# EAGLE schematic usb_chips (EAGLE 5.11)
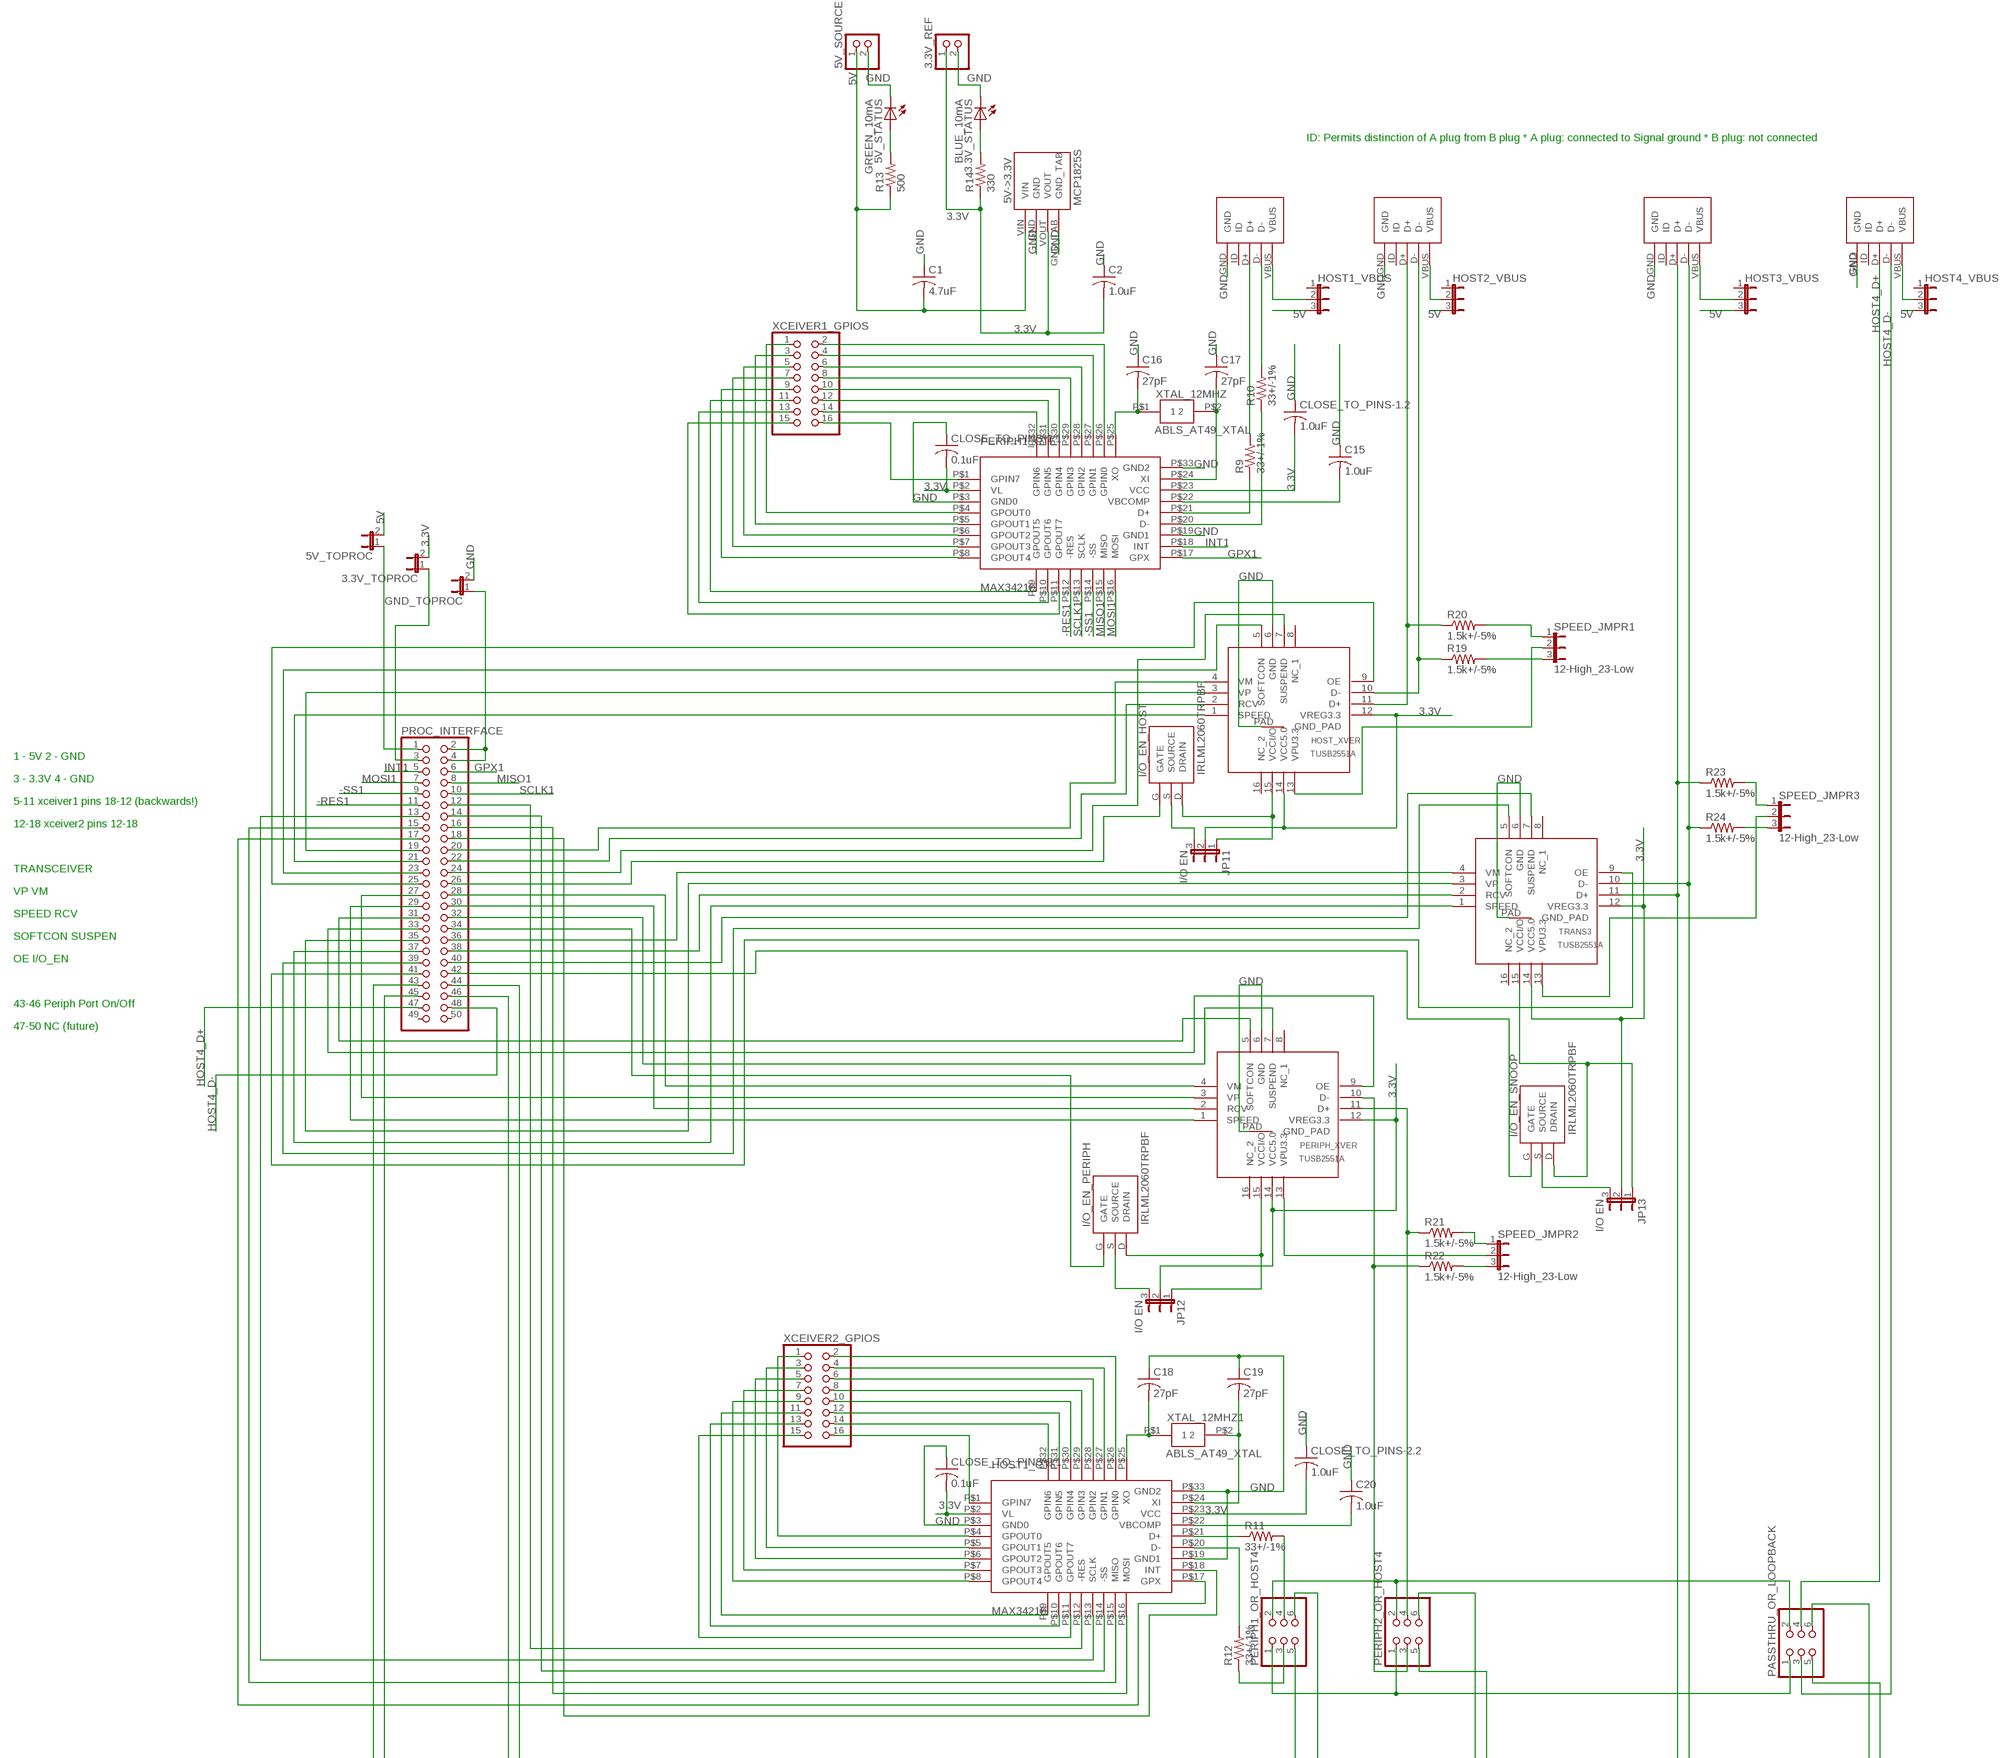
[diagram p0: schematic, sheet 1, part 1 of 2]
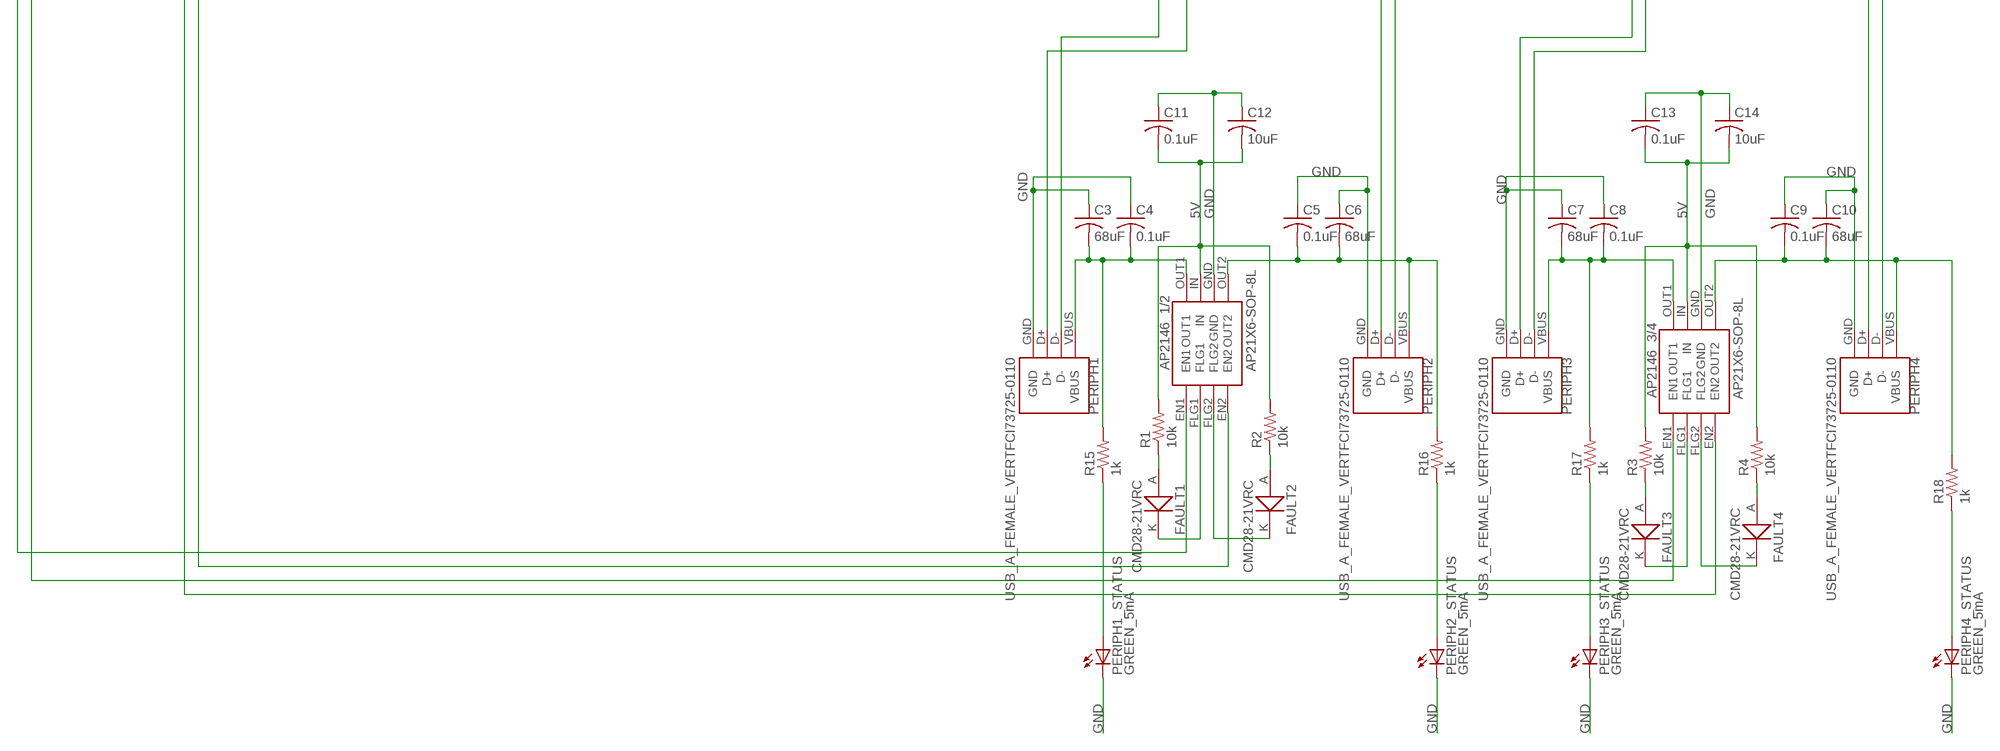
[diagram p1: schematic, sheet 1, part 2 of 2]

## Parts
3.3V_REF  PINHD-1X2  [1X02]
3.3V_STATUS  BLUE_10mA  LEDCHIP-LED0805  [CHIP-LED0805]
3.3V_TOPROC  JP1E  [JP1]
5V->3.3V  MCP1825S  [MCP1825S]
5V_SOURCE  PINHD-1X2  [1X02]
5V_STATUS  GREEN_10mA  LEDCHIP-LED0805  [CHIP-LED0805]
5V_TOPROC  JP1E  [JP1]
AP2146_1/2  AP21X6-SOP-8L  [AP21X6]
AP2146_3/4  AP21X6-SOP-8L  [AP21X6]
C1  4.7uF  C-USC0805  [C0805]
C2  1.0uF  C-USC0805  [C0805]
C3  68uF  C-USC0805  [C0805]
C4  0.1uF  C-USC0805  [C0805]
C5  0.1uF  C-USC0805  [C0805]
C6  68uF  C-USC0805  [C0805]
C7  68uF  C-USC0805  [C0805]
C8  0.1uF  C-USC0805  [C0805]
C9  0.1uF  C-USC0805  [C0805]
C10  68uF  C-USC0805  [C0805]
C11  0.1uF  C-USC0805  [C0805]
C12  10uF  C-USC0805  [C0805]
C13  0.1uF  C-USC0805  [C0805]
C14  10uF  C-USC0805  [C0805]
C15  1.0uF  C-USC0805  [C0805]
C16  27pF  C-USC0805  [C0805]
C17  27pF  C-USC0805  [C0805]
C18  27pF  C-USC0805  [C0805]
C19  27pF  C-USC0805  [C0805]
C20  1.0uF  C-USC0805  [C0805]
CLOSE_TO_PINS-1.1  0.1uF  C-USC0805  [C0805]
CLOSE_TO_PINS-1.2  1.0uF  C-USC0805  [C0805]
CLOSE_TO_PINS-2.1  0.1uF  C-USC0805  [C0805]
CLOSE_TO_PINS-2.2  1.0uF  C-USC0805  [C0805]
FAULT1  CMD28-21VRC  [CMD28-21VRC]
FAULT2  CMD28-21VRC  [CMD28-21VRC]
FAULT3  CMD28-21VRC  [CMD28-21VRC]
FAULT4  CMD28-21VRC  [CMD28-21VRC]
GND_TOPROC  JP1E  [JP1]
HOST1  USB_MICRO_B_FEMALE  [USB_MICRO_B_FEMALE]
HOST1_CTL  MAX3421E  [MAX3421]
HOST1_VBUS  JP2E  [JP2]
HOST2  USB_MICRO_B_FEMALE  [USB_MICRO_B_FEMALE]
HOST2_VBUS  JP2E  [JP2]
HOST3  USB_MICRO_B_FEMALE  [USB_MICRO_B_FEMALE]
HOST3_VBUS  JP2E  [JP2]
HOST4  USB_MICRO_B_FEMALE  [USB_MICRO_B_FEMALE]
HOST4_VBUS  JP2E  [JP2]
HOST_XVER  TUSB2551A  [S-PVQFN-N16]
I/O_EN_HOST  IRLML2060TRPBF  [SOT-23_IRLML2060TRPBF]
I/O_EN_PERIPH  IRLML2060TRPBF  [SOT-23_IRLML2060TRPBF]
I/O_EN_SNOOP  IRLML2060TRPBF  [SOT-23_IRLML2060TRPBF]
JP11  I/O EN  JP2E  [JP2]
JP12  I/O EN  JP2E  [JP2]
JP13  I/O EN  JP2E  [JP2]
PASSTHRU_OR_LOOPBACK  PINHD-2X3  [2X03]
PERIPH1  USB_A_FEMALE_VERTFCI73725-0110  [USB_A_FEMALE_VERT]
PERIPH1_CTL  MAX3421E  [MAX3421]
PERIPH1_OR_HOST4  PINHD-2X3  [2X03]
PERIPH1_STATUS  GREEN_5mA  LEDCHIP-LED0805  [CHIP-LED0805]
PERIPH2  USB_A_FEMALE_VERTFCI73725-0110  [USB_A_FEMALE_VERT]
PERIPH2_OR_HOST4  PINHD-2X3  [2X03]
PERIPH2_STATUS  GREEN_5mA  LEDCHIP-LED0805  [CHIP-LED0805]
PERIPH3  USB_A_FEMALE_VERTFCI73725-0110  [USB_A_FEMALE_VERT]
PERIPH3_STATUS  GREEN_5mA  LEDCHIP-LED0805  [CHIP-LED0805]
PERIPH4  USB_A_FEMALE_VERTFCI73725-0110  [USB_A_FEMALE_VERT]
PERIPH4_STATUS  GREEN_5mA  LEDCHIP-LED0805  [CHIP-LED0805]
PERIPH_XVER  TUSB2551A  [S-PVQFN-N16]
PROC_INTERFACE  PINHD-2X25/90  [2X25/90]
R1  10k  R-US_R0805  [R0805]
R2  10k  R-US_R0805  [R0805]
R3  10k  R-US_R0805  [R0805]
R4  10k  R-US_R0805  [R0805]
R9  33+/-1%  R-US_R0805  [R0805]
R10  33+/-1%  R-US_R0805  [R0805]
R11  33+/-1%  R-US_R0805  [R0805]
R12  33+/-1%  R-US_R0805  [R0805]
R13  500  R-US_R0805  [R0805]
R14  330  R-US_R0805  [R0805]
R15  1k  R-US_R0805  [R0805]
R16  1k  R-US_R0805  [R0805]
R17  1k  R-US_R0805  [R0805]
R18  1k  R-US_R0805  [R0805]
R19  1.5k+/-5%  R-US_R0805  [R0805]
R20  1.5k+/-5%  R-US_R0805  [R0805]
R21  1.5k+/-5%  R-US_R0805  [R0805]
R22  1.5k+/-5%  R-US_R0805  [R0805]
R23  1.5k+/-5%  R-US_R0805  [R0805]
R24  1.5k+/-5%  R-US_R0805  [R0805]
SPEED_JMPR1  12-High_23-Low  JP2E  [JP2]
SPEED_JMPR2  12-High_23-Low  JP2E  [JP2]
SPEED_JMPR3  12-High_23-Low  JP2E  [JP2]
TRANS3  TUSB2551A  [S-PVQFN-N16]
XCEIVER1_GPIOS  PINHD-2X8  [2X08]
XCEIVER2_GPIOS  PINHD-2X8  [2X08]
XTAL_12MHZ  ABLS_AT49_XTAL  [ABLS_AT49_XTAL]
XTAL_12MHZ1  ABLS_AT49_XTAL  [ABLS_AT49_XTAL]

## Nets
3.3V: 3.3V_REF.1 3.3V_TOPROC.2 5V->3.3V.VOUT C2.2 CLOSE_TO_PINS-1.1.2 CLOSE_TO_PINS-1.2.2 CLOSE_TO_PINS-2.1.2 CLOSE_TO_PINS-2.2.2 HOST1_CTL.P$2(VL) HOST1_CTL.P$23(VCC) HOST_XVER.12(VREG3.3) HOST_XVER.14(VCC5.0) JP11.2 JP12.2 JP13.2 PERIPH1_CTL.P$2(VL) PERIPH1_CTL.P$23(VCC) PERIPH_XVER.12(VREG3.3) PERIPH_XVER.14(VCC5.0) R14.1 TRANS3.12(VREG3.3) TRANS3.14(VCC5.0)
5V: 5V->3.3V.VIN 5V_SOURCE.1 5V_TOPROC.2 AP2146_1/2.IN AP2146_3/4.IN C1.2 C11.2 C12.2 C13.2 C14.2 HOST1_VBUS.3 HOST2_VBUS.3 HOST3_VBUS.3 HOST4_VBUS.3 R1.2 R2.2 R3.2 R4.2 R13.1
-RES1: PERIPH1_CTL.P$12(-RES) PROC_INTERFACE.11
-RES2: HOST1_CTL.P$12(-RES) PROC_INTERFACE.12
-SS1: PERIPH1_CTL.P$14(-SS) PROC_INTERFACE.9
-SS2: HOST1_CTL.P$14(-SS) PROC_INTERFACE.14
GND: 3.3V_REF.2 3.3V_STATUS.C 5V->3.3V.GND 5V->3.3V.GND_TAB 5V_SOURCE.2 5V_STATUS.C AP2146_1/2.GND AP2146_3/4.GND C1.1 C2.1 C3.1 C4.1 C5.1 C6.1 C7.1 C8.1 C9.1 C10.1 C11.1 C12.1 C13.1 C14.1 C15.1 C16.1 C17.1 C18.1 C19.1 C20.1 CLOSE_TO_PINS-1.1.1 CLOSE_TO_PINS-1.2.1 CLOSE_TO_PINS-2.1.1 CLOSE_TO_PINS-2.2.1 GND_TOPROC.2 HOST1.GND HOST1_CTL.P$3(GND0) HOST1_CTL.P$19(GND1) HOST1_CTL.P$33(GND2) HOST2.GND HOST3.GND HOST4.GND HOST_XVER.6(GND) HOST_XVER.PAD(GND_PAD) PERIPH1.GND PERIPH1_CTL.P$3(GND0) PERIPH1_CTL.P$19(GND1) PERIPH1_CTL.P$33(GND2) PERIPH1_STATUS.C PERIPH2.GND PERIPH2_STATUS.C PERIPH3.GND PERIPH3_STATUS.C PERIPH4.GND PERIPH4_STATUS.C PERIPH_XVER.6(GND) PERIPH_XVER.PAD(GND_PAD) TRANS3.6(GND) TRANS3.PAD(GND_PAD)
GPX1: PERIPH1_CTL.P$17(GPX) PROC_INTERFACE.6
GPX2: HOST1_CTL.P$17(GPX) PROC_INTERFACE.17
HOST4_D+: HOST4.D+ PASSTHRU_OR_LOOPBACK.4 PROC_INTERFACE.47
HOST4_D-: HOST4.D- PASSTHRU_OR_LOOPBACK.3 PROC_INTERFACE.48
HOST_XVER_D+: HOST2.D+ HOST_XVER.11(D+) R20.1
HOST_XVER_D-: HOST2.D- HOST_XVER.10(D-) R19.1
HOST_XVER_VPU: HOST_XVER.13(VPU3.3) SPEED_JMPR1.2
I/O_EN1: I/O_EN_HOST.G(GATE) PROC_INTERFACE.26
I/O_EN2: I/O_EN_PERIPH.G(GATE) PROC_INTERFACE.34
I/O_EN3: I/O_EN_SNOOP.G(GATE) PROC_INTERFACE.42
INT1: PERIPH1_CTL.P$18(INT) PROC_INTERFACE.5
INT2: HOST1_CTL.P$18(INT) PROC_INTERFACE.18
MISO1: PERIPH1_CTL.P$15(MISO) PROC_INTERFACE.8
MISO2: HOST1_CTL.P$15(MISO) PROC_INTERFACE.15
MOSI1: PERIPH1_CTL.P$16(MOSI) PROC_INTERFACE.7
MOSI2: HOST1_CTL.P$16(MOSI) PROC_INTERFACE.16
N$1: PERIPH1_CTL.P$21(D+) R9.1
N$2: PERIPH1_CTL.P$20(D-) R10.1
N$5: HOST3.D+ PERIPH3.D+ R23.1 TRANS3.11(D+)
N$6: HOST3.D- PERIPH3.D- R24.1 TRANS3.10(D-)
N$9: PASSTHRU_OR_LOOPBACK.5 PERIPH4.D-
N$10: PASSTHRU_OR_LOOPBACK.6 PERIPH4.D+
N$11: PERIPH2.D- PERIPH2_OR_HOST4.5
N$12: PERIPH2.D+ PERIPH2_OR_HOST4.6
N$13: PERIPH2_OR_HOST4.3 PERIPH_XVER.10(D-) R22.1
N$14: PERIPH2_OR_HOST4.4 PERIPH_XVER.11(D+) R21.1
N$15: PASSTHRU_OR_LOOPBACK.2 PERIPH1_OR_HOST4.2 PERIPH2_OR_HOST4.2
N$16: PASSTHRU_OR_LOOPBACK.1 PERIPH1_OR_HOST4.1 PERIPH2_OR_HOST4.1
N$17: HOST1_CTL.P$21(D+) R11.1
N$18: PERIPH1_OR_HOST4.4 R11.2
N$19: HOST_XVER.15(VCCI/O) I/O_EN_HOST.D(DRAIN) JP11.1
N$20: PERIPH1.D- PERIPH1_OR_HOST4.5
N$21: PERIPH1.D+ PERIPH1_OR_HOST4.6
N$22: PERIPH_XVER.13(VPU3.3) SPEED_JMPR2.2
N$23: HOST1.VBUS HOST1_VBUS.2
N$24: HOST2.VBUS HOST2_VBUS.2
N$25: HOST3.VBUS HOST3_VBUS.2
N$26: HOST4.VBUS HOST4_VBUS.2
N$27: I/O_EN_PERIPH.D(DRAIN) JP12.1 PERIPH_XVER.15(VCCI/O)
N$28: I/O_EN_HOST.S(SOURCE) JP11.3
N$29: I/O_EN_PERIPH.S(SOURCE) JP12.3
N$30: I/O_EN_SNOOP.S(SOURCE) JP13.3
N$31: AP2146_1/2.OUT1 C3.2 C4.2 PERIPH1.VBUS R15.2
N$32: AP2146_1/2.OUT2 C5.2 C6.2 PERIPH2.VBUS R16.2
N$33: AP2146_3/4.OUT1 C7.2 C8.2 PERIPH3.VBUS R17.2
N$34: AP2146_3/4.OUT2 C9.2 C10.2 PERIPH4.VBUS R18.2
N$35: PERIPH1_CTL.P$26(GPIN0) XCEIVER1_GPIOS.2
N$36: PERIPH1_CTL.P$27(GPIN1) XCEIVER1_GPIOS.4
N$37: PERIPH1_CTL.P$28(GPIN2) XCEIVER1_GPIOS.6
N$38: PERIPH1_CTL.P$29(GPIN3) XCEIVER1_GPIOS.8
N$39: PERIPH1_CTL.P$30(GPIN4) XCEIVER1_GPIOS.10
N$40: PERIPH1_CTL.P$31(GPIN5) XCEIVER1_GPIOS.12
N$41: PERIPH1_CTL.P$32(GPIN6) XCEIVER1_GPIOS.14
N$42: PERIPH1_CTL.P$1(GPIN7) XCEIVER1_GPIOS.16
N$43: PERIPH1_CTL.P$4(GPOUT0) XCEIVER1_GPIOS.1
N$44: PERIPH1_CTL.P$5(GPOUT1) XCEIVER1_GPIOS.3
N$45: PERIPH1_CTL.P$6(GPOUT2) XCEIVER1_GPIOS.5
N$46: PERIPH1_CTL.P$7(GPOUT3) XCEIVER1_GPIOS.7
N$47: PERIPH1_CTL.P$8(GPOUT4) XCEIVER1_GPIOS.9
N$48: PERIPH1_CTL.P$9(GPOUT5) XCEIVER1_GPIOS.11
N$49: PERIPH1_CTL.P$10(GPOUT6) XCEIVER1_GPIOS.13
N$50: PERIPH1_CTL.P$11(GPOUT7) XCEIVER1_GPIOS.15
N$51: HOST1_CTL.P$26(GPIN0) XCEIVER2_GPIOS.2
N$52: HOST1_CTL.P$27(GPIN1) XCEIVER2_GPIOS.4
N$53: HOST1_CTL.P$28(GPIN2) XCEIVER2_GPIOS.6
N$54: HOST1_CTL.P$29(GPIN3) XCEIVER2_GPIOS.8
N$55: HOST1_CTL.P$30(GPIN4) XCEIVER2_GPIOS.10
N$56: HOST1_CTL.P$31(GPIN5) XCEIVER2_GPIOS.12
N$57: HOST1_CTL.P$32(GPIN6) XCEIVER2_GPIOS.14
N$58: HOST1_CTL.P$1(GPIN7) XCEIVER2_GPIOS.16
N$59: HOST1_CTL.P$4(GPOUT0) XCEIVER2_GPIOS.1
N$60: HOST1_CTL.P$5(GPOUT1) XCEIVER2_GPIOS.3
N$61: HOST1_CTL.P$6(GPOUT2) XCEIVER2_GPIOS.5
N$62: HOST1_CTL.P$7(GPOUT3) XCEIVER2_GPIOS.7
N$63: HOST1_CTL.P$8(GPOUT4) XCEIVER2_GPIOS.9
N$64: HOST1_CTL.P$9(GPOUT5) XCEIVER2_GPIOS.11
N$65: HOST1_CTL.P$10(GPOUT6) XCEIVER2_GPIOS.13
N$66: HOST1_CTL.P$11(GPOUT7) XCEIVER2_GPIOS.15
N$67: FAULT3.A R3.1
N$68: AP2146_3/4.FLG1 FAULT3.K
N$69: FAULT4.A R4.1
N$70: AP2146_3/4.FLG2 FAULT4.K
N$71: AP2146_1/2.FLG1 FAULT1.K
N$72: FAULT2.A R2.1
N$73: FAULT1.A R1.1
N$74: AP2146_1/2.FLG2 FAULT2.K
N$75: C15.2 PERIPH1_CTL.P$22(VBCOMP)
N$76: HOST1.D+ R9.2
N$77: HOST1.D- R10.2
N$78: HOST1_CTL.P$20(D-) R12.2
N$79: PERIPH1_OR_HOST4.3 R12.1
N$84: 5V_TOPROC.1 PROC_INTERFACE.1
N$85: 3.3V_TOPROC.1 PROC_INTERFACE.3
N$86: 5V_STATUS.A R13.2
N$87: 3.3V_STATUS.A R14.2
N$88: PERIPH4_STATUS.A R18.1
N$89: GND_TOPROC.1 PROC_INTERFACE.2 PROC_INTERFACE.4
N$90: PERIPH3_STATUS.A R17.1
N$91: PERIPH2_STATUS.A R16.1
N$92: PERIPH1_STATUS.A R15.1
N$94: R19.2 SPEED_JMPR1.3
N$95: R20.2 SPEED_JMPR1.1
N$96: SPEED_JMPR3.2 TRANS3.13(VPU3.3)
N$97: R24.2 SPEED_JMPR3.3
N$98: R23.2 SPEED_JMPR3.1
N$99: R22.2 SPEED_JMPR2.3
N$100: I/O_EN_SNOOP.D(DRAIN) JP13.1 TRANS3.15(VCCI/O)
N$101: R21.2 SPEED_JMPR2.1
N$102: C20.2 HOST1_CTL.P$22(VBCOMP)
OE1: HOST_XVER.9(OE) PROC_INTERFACE.25
OE2: PERIPH_XVER.9(OE) PROC_INTERFACE.33
OE3: PROC_INTERFACE.41 TRANS3.9(OE)
PERIPH1_CTL: AP2146_1/2.EN1 PROC_INTERFACE.43
PERIPH2_CTL: AP2146_1/2.EN2 PROC_INTERFACE.44
PERIPH3_CTL: AP2146_3/4.EN1 PROC_INTERFACE.45
PERIPH4_CTL: AP2146_3/4.EN2 PROC_INTERFACE.46
RCV1: HOST_XVER.2(RCV) PROC_INTERFACE.22
RCV2: PERIPH_XVER.2(RCV) PROC_INTERFACE.30
RCV3: PROC_INTERFACE.38 TRANS3.2(RCV)
SCLK1: PERIPH1_CTL.P$13(SCLK) PROC_INTERFACE.10
SCLK2: HOST1_CTL.P$13(SCLK) PROC_INTERFACE.13
SOFTCON1: HOST_XVER.5(SOFTCON) PROC_INTERFACE.23
SOFTCON2: PERIPH_XVER.5(SOFTCON) PROC_INTERFACE.31
SOFTCON3: PROC_INTERFACE.39 TRANS3.5(SOFTCON)
SPEED1: HOST_XVER.1(SPEED) PROC_INTERFACE.21
SPEED2: PERIPH_XVER.1(SPEED) PROC_INTERFACE.29
SPEED3: PROC_INTERFACE.37 TRANS3.1(SPEED)
SUSPEND1: HOST_XVER.7(SUSPEND) PROC_INTERFACE.24
SUSPEND2: PERIPH_XVER.7(SUSPEND) PROC_INTERFACE.32
SUSPEND3: PROC_INTERFACE.40 TRANS3.7(SUSPEND)
VM1: HOST_XVER.4(VM) PROC_INTERFACE.20
VM2: PERIPH_XVER.4(VM) PROC_INTERFACE.28
VM3: PROC_INTERFACE.36 TRANS3.4(VM)
VP1: HOST_XVER.3(VP) PROC_INTERFACE.19
VP2: PERIPH_XVER.3(VP) PROC_INTERFACE.27
VP3: PROC_INTERFACE.35 TRANS3.3(VP)
XI1: C17.2 PERIPH1_CTL.P$24(XI) XTAL_12MHZ.P$2
XI2: C19.2 HOST1_CTL.P$24(XI) XTAL_12MHZ1.P$2
XO1: C16.2 PERIPH1_CTL.P$25(XO) XTAL_12MHZ.P$1
XO2: C18.2 HOST1_CTL.P$25(XO) XTAL_12MHZ1.P$1
Unconnected: HOST1.ID HOST1_VBUS.1 HOST2.ID HOST2_VBUS.1 HOST3.ID HOST3_VBUS.1 HOST4.ID HOST4_VBUS.1 HOST_XVER.8(NC_1) HOST_XVER.16(NC_2) PERIPH_XVER.8(NC_1) PERIPH_XVER.16(NC_2) PROC_INTERFACE.49 PROC_INTERFACE.50 TRANS3.8(NC_1) TRANS3.16(NC_2)

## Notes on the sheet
- ID: Permits distinction of A plug from B plug * A plug: connected to Signal ground * B plug: not connected
- 1 - 5V 2 - GND
- 3 - 3.3V 4 - GND
- 5-11 xceiver1 pins 18-12 (backwards!)
- 12-18 xceiver2 pins 12-18
- TRANSCEIVER
- VP VM
- SPEED RCV
- SOFTCON SUSPEN
- OE I/O_EN
- 43-46 Periph Port On/Off
- 47-50 NC (future)

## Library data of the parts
3.3V_REF 5V_SOURCE = pinhead:PINHD-1X2: PIN HEADER
3.3V_STATUS 5V_STATUS PERIPH1_STATUS PERIPH2_STATUS PERIPH3_STATUS PERIPH4_STATUS = led:LED: LED
3.3V_TOPROC 5V_TOPROC GND_TOPROC = jumper:JP1E: JUMPER
5V->3.3V = usb:MCP1825S
AP2146_1/2 AP2146_3/4 = usb:AP21X6
C1-C20 CLOSE_TO_PINS-1.1 CLOSE_TO_PINS-1.2 CLOSE_TO_PINS-2.1 CLOSE_TO_PINS-2.2 = resistor:C-US: CAPACITOR, American symbol
FAULT1-FAULT4 = usb:CMD28-21VRC
HOST1-HOST4 = usb:USB_MICRO_B_FEMALE
HOST1_CTL PERIPH1_CTL = usb:MAX3421E
HOST1_VBUS HOST2_VBUS HOST3_VBUS HOST4_VBUS JP11-JP13 SPEED_JMPR1-SPEED_JMPR3 = jumper:JP2E: JUMPER
HOST_XVER PERIPH_XVER TRANS3 = usb:TUSB2551
I/O_EN_HOST I/O_EN_PERIPH I/O_EN_SNOOP = usb:IRLML2060TRPBF
PASSTHRU_OR_LOOPBACK PERIPH1_OR_HOST4 PERIPH2_OR_HOST4 = pinhead:PINHD-2X3: PIN HEADER
PERIPH1-PERIPH4 = usb:USB_A_FEMALE_VERT
PROC_INTERFACE = pinhead:PINHD-2X25: PIN HEADER
R1-R4 R9-R24 = resistor:R-US_: RESISTOR, American symbol
XCEIVER1_GPIOS XCEIVER2_GPIOS = pinhead:PINHD-2X8: PIN HEADER
XTAL_12MHZ XTAL_12MHZ1 = usb:ABLS_AT49_XTAL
